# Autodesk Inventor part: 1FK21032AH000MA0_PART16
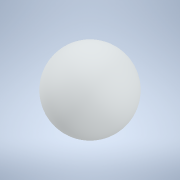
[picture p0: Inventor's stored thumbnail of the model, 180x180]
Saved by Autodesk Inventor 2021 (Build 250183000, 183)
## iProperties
Created: 2025-04
Part Number: 1FK21032AH000MA0_PART16
Material: Generic
Catalog Web Link: www.3dfindit.com
Description: -Servo synchronous motor
Document SubType Name: Modeling
Designer: psAdmin
Mass: 0.113097 g
Surface Area: 1.13097 cm^2
Volume: 0.113097 cm^3
Density: 1 g/cm^3
Appearance: PSOLRGB-212-217-219
Category: PARTsolutions
Title: 1FK21032AH000MA0_PART16
Author: Cadenas PARTsolutions
Comments: Servo synchronous motor
Sending System: PARTsolutions
Preprocessor: ST-DEVELOPER v19.3
PSOL_IDENT_0: {$CADENAS_DATA/23d-libs/siemens_ag/_cat_/45/10/1fk21032ah000ma0.prj},216 {VTYP=3D},{NB=1FK21032AH000
PSOL_IDENT_1: MA0_PART16},{LINA=1FK21032AH000MA0_PART16},{NN=1FK21032AH000MA0_PART16},{NOPRJ=TRUE},{DATE=19.08.202
PSOL_IDENT_2: 5 14:00:35},{GEOMDATE=30.07.2025 02:02:03},{VERSION=},{LINEID=10},{WBVAR=},{WBNUMERIC=}  {NB=1FK2103
PSOL_IDENT_3: 2AH000MA0_PART16},{LINA=1FK21032AH000MA0_PART16},{KT=DUMMY},{PREVIEW=../../../_pool_/14/8e/p_d211_xx
PSOL_IDENT_4: _00426j.png},{DESCSHORT=SIMOTICS S-1FK2 HD, SINAMICS S210 3AC 400V-480V, 0.59 Nm, 4500 rpm},{DESCLON
PSOL_IDENT_5: G=SIMOTICS S-1FK2 HD servo motor M0=0.64 Nm; PN = 0.28 kW at nN=4500 rpm (380-480 V); PN = 0.167 kW
PSOL_IDENT_6: at nN=2500 rpm (200-240 V); degree of protection IP64; cylindrical shaft D14 x 30 mm; absolute encod
PSOL_IDENT_7: er 22-bit + 12-bit multiturn (encoder AM22DQC); with OCC interface; plug size M17, rotatable; SIMOTI
PSOL_IDENT_8: CS S-1FK2 servomotorfor a wide range of uses in industrial environments. SIMOTICS S‑1FK2 servomotors
PSOL_IDENT_9: are compact synchronous motors with a high dynamic performance that set themselves apart as a resul
PSOL_IDENT_10: t of their high power density, degree of protection and overload capability. The motors are availabl
PSOL_IDENT_11: e in two variants: as High Dynamic variant (highest dynamic performance as a result of the low intri
PSOL_IDENT_12: nsic moment of inertia for applications demanding a high dynamic performance with low moved masses)
PSOL_IDENT_13: - and as Compact variant (precise and stable closed-loop control for medium up to large moved masses
PSOL_IDENT_14: as a result of a medium intrinsic moment of inertia). SIMOTICSS‑1FK2 servomotors fully exploit thei
PSOL_IDENT_15: r strengths in a system with the SINAMICSS210 frequency converter and simple connection using the on
PSOL_IDENT_16: e cable connection (OCC). Advantages include the short control and positioning times, fast and preci
PSOL_IDENT_17: se correction of disturbing quantities as well as stable control with a high dynamic performance. Th
PSOL_IDENT_18: e servo motors can be configured to address a wide range of requirements. For example with and witho
PSOL_IDENT_19: ut holding brake, IP64 or IP65 degree of protection, singleturn or multiturn absolute encoders - to
PSOL_IDENT_20: name just a few. Further, the servomotors are available in different shaft heights extending from 20
PSOL_IDENT_21: to 100. A shaft sealing ring is available to achieve an IP65 degree of protection and for subsequen
PSOL_IDENT_22: t mounting at the motor or as spare part. SIMOTICS - the optimum motor for each and every motion con
PSOL_IDENT_23: trol application.},{INTNO=195125335004},{SUPPLIERALTNO=1FK2103-2AH00-0MA0},{MANUID=1FK21032AH000MA0}
PSOL_IDENT_24: ,{MANUNAME=Siemens},{MANUTYPEDESC=SYNCHRONOUS MOTOR 1FK2 HD 0,64 NM},{AAU732=SIMOTICS},{AAO057=S-1FK
PSOL_IDENT_25: 2},{AAU734=SIMOTICS S-1FK2 HD servo motor M0=0.64 Nm; PN = 0.28 kW at nN=4500 rpm (380-480 V); PN =
PSOL_IDENT_26: 0.167 kW at nN=2500 rpm (200-240 V); degree of protection IP64; cylindrical shaft D14 x 30 mm; absol
PSOL_IDENT_27: ute encoder 22-bit + 12-bit multiturn (encoder AM22DQC); with OCC interface; plug size M17, rotatabl
PSOL_IDENT_28: e;},{AAW338=SYNCHRONOUS MOTOR 1FK2 HD 0,64 NM},{AAO742=SIMOTICS},{AAO663=4034106444624},{NOCUPEROU=1
PSOL_IDENT_29: },{PRICEQUANTITY=1},{QUANTITYMIN=1},{QUANTITYINT=1},{CTN=85015100},{COO=RO},{AAO676=1FK2103-2AH00-0M
PSOL_IDENT_30: A0},{AAO677=Siemens AG},{ORDERUNIT=C62},{CONTENTUNIT=C62}
NB: 1FK21032AH000MA0_PART16
NT: Servo synchronous motor
NBSYN: $MANUID._PART16
LINA: 1FK21032AH000MA0_PART16
CATALOG: SIEMENS
PREVIEW: ../../../_pool_/14/8e/p_d211_xx_00426j.png
DESCSHORT: SIMOTICS S-1FK2 HD, SINAMICS S210 3AC 400V-480V, 0.59 Nm, 4500 rpm
DESCLONG: SIMOTICS S-1FK2 HD servo motor M0=0.64 Nm; PN = 0.28 kW at nN=4500 rpm (380-480 V); PN = 0.167 kW at nN=2500 rpm (200-240 V); degree of protection IP64; cylindr
INTNO: 195125335004
SUPPLIERALTNO: 1FK2103-2AH00-0MA0
MANUID: 1FK21032AH000MA0
MANUNAME: Siemens
MANUTYPEDESC: SYNCHRONOUS MOTOR 1FK2 HD 0,64 NM
AAU732: SIMOTICS
AAO057: S-1FK2
AAU734: SIMOTICS S-1FK2 HD servo motor M0=0.64 Nm; PN = 0.28 kW at nN=4500 rpm (380-480 V); PN = 0.167 kW at nN=2500 rpm (200-240 V); degree of protection IP64; cylindr
AAW338: SYNCHRONOUS MOTOR 1FK2 HD 0,64 NM
AAO742: SIMOTICS
AAO663: 4034106444624.0
NOCUPEROU: 1
PRICEQUANTITY: 1
QUANTITYMIN: 1
QUANTITYINT: 1
CTN: 85015100
COO: RO
ARTICLENO: 1FK21032AH000MA0_PART16
BOMINFO: 1FK21032AH000MA0_PART16
CREATOR: CADENAS GmbH
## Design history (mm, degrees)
feature "2025_04_17_15_00_20_0760"
body "Solid1"
